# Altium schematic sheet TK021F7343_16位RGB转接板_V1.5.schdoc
size 292 x 205 mm; Device: A_A4; Symbol: A_A4; Name: A_A4; @Project Name: TK021F2699-RGB_转接板_椭圆-24位; REV: 1.0; Date: 2022-07-25; Sheet: 1/1; Draw By: zhouao; Company: NULL Studio; Convert to PCB: yes; Add into BOM: yes; Width: 1150; Height: 807; Region Start: 1; X Region Count: 1; Y Region Count: 1; Title Block Position: 3; @Page No: 1; @Page Count: 1; @Schematic Name: TK021F7343_16位RGB转接板_2; @Board Name: TK021F7343_16位RGB转接板_经理改好的板; @Update Date: 2025-08-27; @Create Time: 19:40:00; @Update Time: 19:40:00; @Page Name: Sheet_1; @Create Date: 2025-08-27
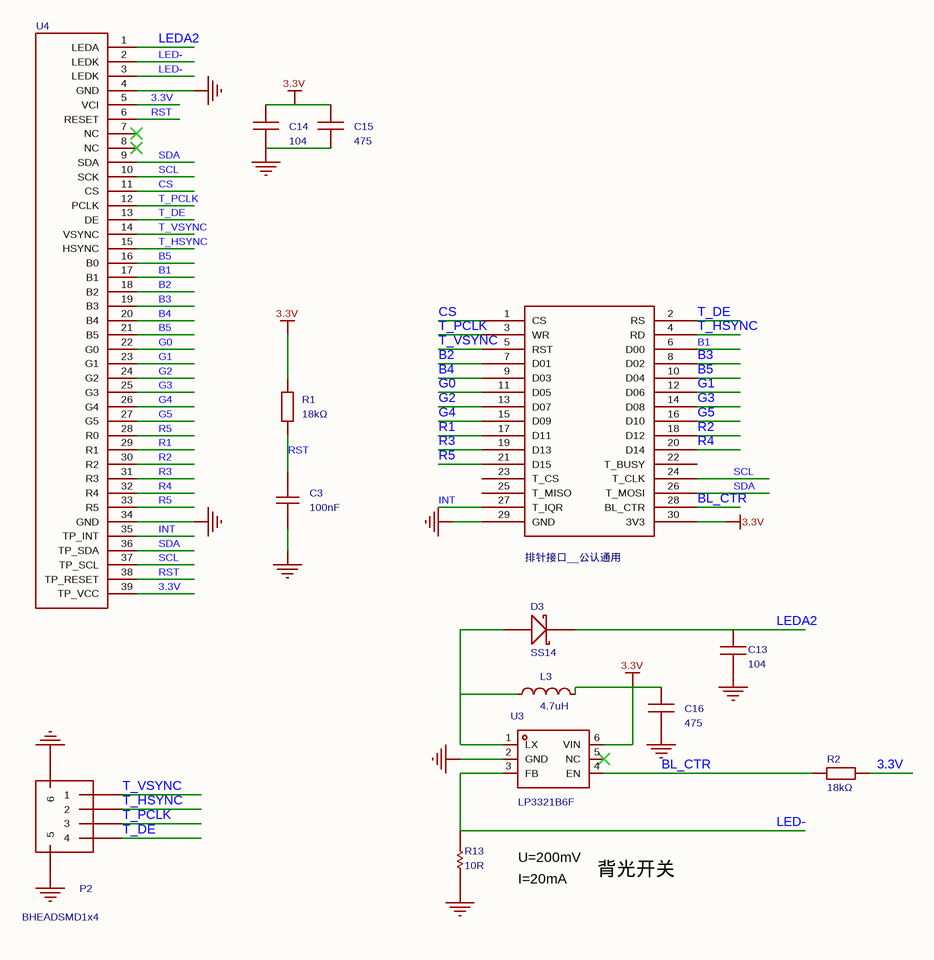
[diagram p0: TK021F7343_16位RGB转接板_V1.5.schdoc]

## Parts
C3  100nF  [C0603]
C13  104  [C0603-1]
C14  104  [C0603-1]
C15  475  [C0603-2]
C16  475  [C0603-2]
D3  SS14  [SOD123]
L3  4.7uH  [IND-SMD_L3.0-W3.0_FNR30XXS]
P2  BHEADSMD1x4  [BHEADSMD1x4]
R1  18kΩ  [R0603]
R2  18kΩ  [R0603]
R13  10R  [R0603]
U3  LP3321B6F  [SOT-23-6_L2.9-W1.6-P0.95-LS2.8-BR]
U4  (no value)  [TK021F7343-39P]
公认通用1  排针接口__公认通用  [P_Head_2x15]

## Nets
3.3V: C14.1 C15.1 C16.1 L3.2 R1.2 R2.2 U3.6(VIN) U4.5(VCI) U4.39(TP_VCC) 公认通用1.30(3V3)
GND: C3.2 C13.2 C14.2 C15.2 C16.2 P2.5 P2.6 R13.2 U3.2(GND) U4.4(GND) U4.34(GND) 公认通用1.29(GND)
B1: U4.17(B1) 公认通用1.6(D00)
B2: U4.18(B2) 公认通用1.7(D01)
B3: U4.19(B3) 公认通用1.8(D02)
B4: U4.20(B4) 公认通用1.9(D03)
B5: U4.16(B0) U4.21(B5) 公认通用1.10(D04)
BL_CTR: R2.1 U3.4(EN) 公认通用1.28(BL_CTR)
CS: U4.11(CS) 公认通用1.1(CS)
G0: U4.22(G0) 公认通用1.11(D05)
G1: U4.23(G1) 公认通用1.12(D06)
G2: U4.24(G2) 公认通用1.13(D07)
G3: U4.25(G3) 公认通用1.14(D08)
G4: U4.26(G4) 公认通用1.15(D09)
G5: U4.27(G5) 公认通用1.16(D10)
INT: U4.35(TP_INT) 公认通用1.27(T_IQR)
LED-: R13.1 U3.3(FB) U4.2(LEDK) U4.3(LEDK)
LEDA2: C13.1 D3.2(K) U4.1(LEDA)
R1: U4.29(R1) 公认通用1.17(D11)
R2: U4.30(R2) 公认通用1.18(D12)
R3: U4.31(R3) 公认通用1.19(D13)
R4: U4.32(R4) 公认通用1.20(D14)
R5: U4.28(R0) U4.33(R5) 公认通用1.21(D15)
RST: C3.1 R1.1 U4.6(RESET) U4.38(TP_RESET)
SCL: U4.10(SCK) U4.37(TP_SCL) 公认通用1.24(T_CLK)
SDA: U4.9(SDA) U4.36(TP_SDA) 公认通用1.26(T_MOSI)
T_DE: P2.4 U4.13(DE) 公认通用1.2(RS)
T_HSYNC: P2.2 U4.15(HSYNC) 公认通用1.4(RD)
T_PCLK: P2.3 U4.12(PCLK) 公认通用1.3(WR)
T_VSYNC: P2.1 U4.14(VSYNC) 公认通用1.5(RST)
NetD3_1: D3.1(A) L3.1 U3.1(LX)

Not connected (* = marked no-connect by the designer): U3 5(NC)*; U4 7(NC)* 8(NC)*; 公认通用1 22(T_BUSY) 23(T_CS) 25(T_MISO)

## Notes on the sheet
- U=200mV
- I=20mA
- 背光开关

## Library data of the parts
C3 = CC0603KRX7R9BB104: 容值:100nF;精度:±10%;额定电压:50V;材质(温度系数):X7R;; Manufacturer: YAGEO(国巨); Symbol: CC0603KRX7R9BB104_1; AddInBom: yes; ModelId: ac125912035d415993ca9572d50418b1; ModelName: C0603_L1.6-W0.8-H0.8; ModelTransform: 62.992,31.496,0,0,0,0,0,0,0; Tolerance: ±10%; Voltage Rated: 50V; Temperature Coefficient: X7R
C13 = 104: Origin Footprint 1: C0603-2; Symbol: cap; Origin Footprint 2: C0402-1; Origin Footprint 3: C0402-2; Origin Footprint 4: C0402-3; Origin Footprint 6: C0603-3; Origin Footprint 7: C0805-1; Origin Footprint 8: C0805-2; Origin Footprint 9: C0805-3; Origin Footprint 10: Case B 3528; Reuse Block: 背光升压输入电源可以用3.3V---5V; Group ID: 1; Channel ID: $1e187; AddInBom: yes
C14 = 104: Symbol: cap; Origin Footprint 2: C0402-2; Origin Footprint 3: C0402-3; Origin Footprint 5: C0603-2; Origin Footprint 6: C0603-3; Origin Footprint 7: C0805-1; Origin Footprint 8: C0805-2; Origin Footprint 9: C0805-3; Origin Footprint 10: Case B 3528; Reuse Block: 背光升压输入电源可以用3.3V---5V; Group ID: 1; Channel ID: $1e88; AddInBom: yes
C15 C16 = 475: Symbol: cap; Origin Footprint 2: C0402-1; Origin Footprint 3: C0402-2; Origin Footprint 4: C0402-3; Origin Footprint 5: C0603-1; Origin Footprint 6: C0603-3; Origin Footprint 7: C0805-1; Origin Footprint 8: C0805-2; Origin Footprint 9: C0805-3; Origin Footprint 10: Case B 3528; Reuse Block: 背光升压输入电源可以用3.3V---5V; Group ID: 1; Channel ID: $1e118; AddInBom: yes
D3 = SS14: Schottky Diode; Symbol: D Schottky; Origin Footprint 2: SMB; Reuse Block: 背光升压输入电源可以用3.3V---5V; Group ID: 1; Channel ID: $1e306; AddInBom: yes
L3 = SWPA3015S4R7MT: 类型:-;电感值:4.7uH;精度:±20%;额定电流:1.09A;饱和电流(Isat):1.4A;; Manufacturer: Sunlord(顺络); Tolerance: ±20%; Rated Current: 1.09A; DC Resistance (DCR): 163mΩ; Reuse Block: 背光升压输入电源可以用3.3V---5V; Group ID: 1; Channel ID: $1e226; AddInBom: yes; ModelId: 822d71758aa744dca2559abd61137eb2; ModelName: IND-SMD_L3.0-W3.0-H1.5_FNR30XXS; ModelTransform: 118.11,118.11,0,90,0,0,0,0,0; Saturation Current (Isat): 1.4A
P2 = BHEADSMD1x4: AddInBom: yes
R1 R2 = 0603WAF1802T5E: 电阻类型:厚膜电阻;阻值:18kΩ;精度:±1%;功率:100mW;最大工作电压:75V;温度系数:±100ppm/℃;; Manufacturer: UNI-ROYAL(厚声); Symbol: 0603WAF1802T5E_1; AddInBom: yes; ModelId: fc143cca1e79419f9cd78b61e9279f080819f05c4eef4c71ace90d822a990e87; ModelTransform: 31.8897,63.7794,0,90,0,0,0,0,0; Tolerance: ±1%; Power(Watts): 100mW; Overload Voltage (Max): 75V
R13 = 5R1: Symbol: Resistor; Reuse Block: 背光升压输入电源可以用3.3V---5V; Group ID: 1; Channel ID: $1e148; AddInBom: yes
U3 = LP3321B6F: Manufacturer: LOWPOWER(微源半导体); Reuse Block: 背光升压输入电源可以用3.3V---5V; Group ID: 1; Channel ID: $1e263; AddInBom: yes; ModelId: 18da8f6c14a34920b3e136b5c401a119; ModelName: SOT-23-6_L2.9-W1.6-H1.5-LS2.8-P0.95; ModelTransform: 110.73671,114.173,0,180,0,0,0.001,-0.003,0
U4 = TK021F7343-39P: AddInBom: yes; ModelTransform: 0, 0, 0, 0, 0, 0, 0, 0, 0
公认通用1 = 排针接口__公认通用: Symbol: LCD_common; AddInBom: yes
